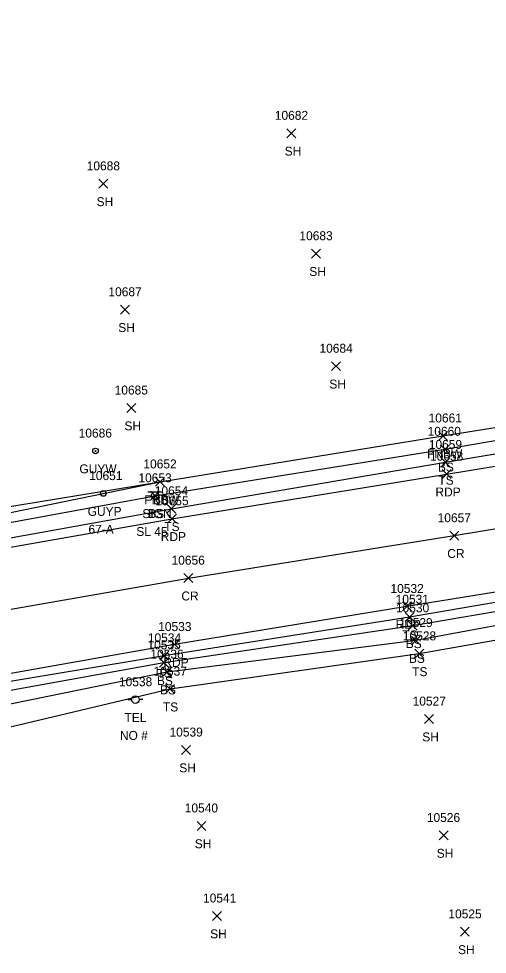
# Model space of a CAD drawing. Extents: x 1475671 to 1477951, y 592661 to 593821.
# Drawn here: x 1475962.2 to 1476066.9, y 592891.1 to 593100.2 of the extents above; entities that cross this region are included whole.
import ezdxf

# ---------------------------------------------------------------- set-up
doc = ezdxf.new("R2010")
doc.units = 0
for name, color, linetype in [('L_A', 7, 'Continuous'), ('L_I', 7, 'Continuous'), ('L_TIC', 7, 'Continuous'), ('LELB', 7, 'Continuous'), ('LFNC', 7, 'Continuous'), ('P_A', 7, 'Continuous'), ('P_I', 7, 'Continuous'), ('P_TIC', 7, 'Continuous'), ('PET', 7, 'Continuous'), ('PRC', 7, 'Continuous'), ('S_A', 7, 'Continuous'), ('S_C', 7, 'Continuous'), ('S_I', 7, 'Continuous'), ('SSGN', 7, 'Continuous'), ('U_A', 7, 'Continuous'), ('U_C', 7, 'Continuous'), ('U_I', 7, 'Continuous'), ('UP', 7, 'Continuous'), ('UPGW', 7, 'Continuous')]:
    doc.layers.add(name, color=color, linetype=linetype)

msp = doc.modelspace()

# ---------------------------------------------------------------- linework, layer by layer
at = {"layer": 'L_TIC'}
for points in [[(1476022.14, 593073.57), (1476024.14, 593075.57)], [(1476024.14, 593073.57), (1476022.14, 593075.57)], [(1475980.1, 593062.28), (1475982.1, 593064.28)], [(1475982.1, 593062.28), (1475980.1, 593064.28)], [(1476027.65, 593046.67), (1476029.65, 593048.67)], [(1476029.65, 593046.67), (1476027.65, 593048.67)], [(1475984.95, 593034.15), (1475986.95, 593036.15)], [(1475986.95, 593034.15), (1475984.95, 593036.15)], [(1476032.12, 593021.52), (1476034.12, 593023.52)], [(1476034.12, 593021.52), (1476032.12, 593023.52)], [(1475986.34, 593012.18), (1475988.34, 593014.18)], [(1475988.34, 593012.18), (1475986.34, 593014.18)], [(1476055.99, 593005.94), (1476057.99, 593007.94)], [(1476057.99, 593005.94), (1476055.99, 593007.94)], [(1476056.44, 593002.96), (1476058.44, 593004.96)], [(1476058.44, 593002.96), (1476056.44, 593004.96)], [(1476056.58, 593000.03), (1476058.58, 593002.03)], [(1476058.58, 593000.03), (1476056.58, 593002.03)], [(1475992.78, 592995.67), (1475994.78, 592997.67)], [(1475994.78, 592995.67), (1475992.78, 592997.67)], [(1475992.78, 592995.67), (1475994.78, 592997.67)], [(1475994.78, 592995.67), (1475992.78, 592997.67)], [(1475991.67, 592992.57), (1475993.67, 592994.57)], [(1475993.67, 592992.57), (1475991.67, 592994.57)], [(1475995.32, 592989.67), (1475997.32, 592991.67)], [(1475997.32, 592989.67), (1475995.32, 592991.67)], [(1476048.54, 592965.45), (1476050.54, 592967.45)], [(1476050.54, 592965.45), (1476048.54, 592967.45)], [(1476049.25, 592963.51), (1476051.25, 592965.51)], [(1476051.25, 592963.51), (1476049.25, 592965.51)], [(1476049.95, 592960.21), (1476051.95, 592962.21)], [(1476051.95, 592960.21), (1476049.95, 592962.21)], [(1476050.72, 592957.25), (1476052.72, 592959.25)], [(1476052.72, 592957.25), (1476050.72, 592959.25)], [(1475993.64, 592955.24), (1475995.64, 592957.24)], [(1475995.64, 592955.24), (1475993.64, 592957.24)], [(1475993.72, 592956.82), (1475995.72, 592958.82)], [(1475995.72, 592956.82), (1475993.72, 592958.82)], [(1475994.34, 592953.17), (1475996.34, 592955.17)], [(1475996.34, 592953.17), (1475994.34, 592955.17)], [(1475995.01, 592949.36), (1475997.01, 592951.36)], [(1475997.01, 592949.36), (1475995.01, 592951.36)], [(1476052.9, 592942.67), (1476054.9, 592944.67)], [(1476054.9, 592942.67), (1476052.9, 592944.67)], [(1475998.58, 592935.75), (1476000.58, 592937.75)], [(1476000.58, 592935.75), (1475998.58, 592937.75)], [(1476002.05, 592918.79), (1476004.05, 592920.79)], [(1476004.05, 592918.79), (1476002.05, 592920.79)], [(1476056.14, 592916.66), (1476058.14, 592918.66)], [(1476058.14, 592916.66), (1476056.14, 592918.66)], [(1476005.5, 592898.66), (1476007.5, 592900.66)], [(1476007.5, 592898.66), (1476005.5, 592900.66)], [(1476060.9, 592895.12), (1476062.9, 592897.12)], [(1476062.9, 592895.12), (1476060.9, 592897.12)]]:
    msp.add_lwpolyline(points, dxfattribs=at)
at = {"layer": 'LELB'}
for points in [[(1475681.97, 592926.29), (1475693.99, 592930.92), (1475717.71, 592935.95), (1475764.49, 592948.74), (1475792.84, 592955.38), (1475826.76, 592965.2), (1475839.14, 592967.57), (1475847.44, 592968.45), (1475896, 592975.83), (1475948.75, 592985.5), (1475992.67, 592993.57), (1476057.44, 593003.96), (1476113.1, 593013.57), (1476163.64, 593021.28), (1476215.98, 593029.82), (1476272.69, 593037.85), (1476322.72, 593046.24), (1476372.45, 593058.02), (1476374.59, 593060.62), (1476398.56, 593065.83), (1476415.47, 593071.31), (1476457.34, 593084.84)], [(1475681.68, 592929.89), (1475693.99, 592930.92), (1475717.95, 592934.41), (1475766.45, 592946.03), (1475793.6, 592952.64), (1475827.75, 592961.96), (1475839.66, 592963.32), (1475897.61, 592972.89), (1475949.51, 592982.21), (1475996.32, 592990.67), (1476057.58, 593001.03), (1476113.5, 593010.46), (1476164.33, 593018.66), (1476216.45, 593027.16), (1476273.17, 593035.57), (1476322.97, 593043.9), (1476372.64, 593054.79), (1476374.63, 593058.12)], [(1476521.14, 593041.18), (1476464.22, 593030.64), (1476420.77, 593020.64), (1476368.55, 593014.29), (1476359.82, 593012.38), (1476319.88, 593006.6), (1476267.05, 592998.99), (1476216.33, 592991.85), (1476164.01, 592984.31), (1476119.67, 592976.43), (1476101.12, 592973.12), (1476050.25, 592964.51), (1475994.64, 592956.24), (1475948.73, 592947.98), (1475899.49, 592939.5), (1475855.9, 592931.1), (1475802.57, 592920.15), (1475791.75, 592916.74), (1475792.51, 592914.78)], [(1476534.65, 593028.56), (1476525.69, 593019.5), (1476511.54, 593017.85), (1476467.31, 593015.01), (1476422.73, 593008.46), (1476366.85, 593001.28), (1476356.63, 592997.77), (1476347.04, 593000.45), (1476320.8, 592997.35), (1476267.98, 592990.13), (1476216.9, 592984.46), (1476165.76, 592976.73), (1476117.9, 592968.73), (1476100.74, 592966.91), (1476051.72, 592958.25), (1475996.01, 592950.36), (1475948.39, 592939), (1475900.82, 592931.75), (1475857.92, 592923.91), (1475803.59, 592912.34), (1475790.59, 592904.71)], [(1476511.04, 593028.14), (1476465.56, 593023.07), (1476421.22, 593014.7), (1476366.44, 593009.67), (1476355.54, 593008.55), (1476320.37, 593003.18), (1476267.54, 592995.9), (1476216.93, 592987.92), (1476164.84, 592980.53), (1476118, 592971.7), (1476100.88, 592970.48), (1476050.95, 592961.21), (1475995.34, 592954.17), (1475949.24, 592944.73), (1475901.01, 592937.79), (1475856.17, 592929.37), (1475802.39, 592917.73), (1475792.51, 592914.78)], [(1475847.44, 592968.45), (1475847.47, 592971.97), (1475895.33, 592978.11), (1475948.32, 592987.38), (1475993.78, 592996.67)], [(1476119.67, 592976.43), (1476100.91, 592975.21), (1476049.54, 592966.45), (1475994.72, 592957.82), (1475948.15, 592950.07), (1475899.13, 592941.1), (1475855.65, 592932.47), (1475802.49, 592921.46), (1475788.48, 592918.16)]]:
    msp.add_lwpolyline(points, dxfattribs=at)
at = {"layer": 'LFNC'}
msp.add_lwpolyline([(1475680.63, 592937.28), (1475715.61, 592943.34), (1475763.84, 592955.14), (1475791.92, 592961.08), (1475824.89, 592967.76), (1475839.13, 592970.46), (1475847.47, 592971.97), (1475895.02, 592980.45), (1475948.31, 592989.25), (1475993.78, 592996.67), (1476056.99, 593006.94), (1476113.81, 593016.03), (1476164.23, 593025.08), (1476215.07, 593032.59), (1476272.43, 593042.08), (1476322.23, 593049.67), (1476368.09, 593057.49), (1476372.45, 593058.02), (1476374.63, 593058.12), (1476399.83, 593064.01), (1476415.89, 593069.22), (1476458.99, 593083.01), (1476499.73, 593099.84)], dxfattribs=at)
at = {"layer": 'P_TIC'}
for points in [[(1476056.84, 592997.4), (1476058.84, 592999.4)], [(1476058.84, 592997.4), (1476056.84, 592999.4)], [(1475995.45, 592987.43), (1475997.45, 592989.43)], [(1475997.45, 592987.43), (1475995.45, 592989.43)], [(1476058.54, 592983.65), (1476060.54, 592985.65)], [(1476060.54, 592983.65), (1476058.54, 592985.65)], [(1475999.12, 592974.16), (1476001.12, 592976.16)], [(1476001.12, 592974.16), (1475999.12, 592976.16)], [(1476047.95, 592967.83), (1476049.95, 592969.83)], [(1476049.95, 592967.83), (1476047.95, 592969.83)], [(1475996.04, 592959.32), (1475998.04, 592961.32)], [(1475998.04, 592959.32), (1475996.04, 592961.32)]]:
    msp.add_lwpolyline(points, dxfattribs=at)
at = {"layer": 'PET'}
for points in [[(1475682.06, 592924.71), (1475717.58, 592931.68), (1475766.32, 592943.31), (1475794.98, 592949.79), (1475825.77, 592956.33), (1475844.1, 592960.26), (1475899.54, 592970.95), (1475949.72, 592980.21), (1475996.45, 592988.43), (1476057.84, 592998.4), (1476110.05, 593006.96), (1476164.18, 593015.73), (1476216.75, 593023.76), (1476273.83, 593032.32), (1476323.32, 593041.42), (1476373.65, 593052.29), (1476409.24, 593061.35), (1476416.16, 593063.9), (1476459.25, 593078.48), (1476508.39, 593100.17)], [(1476521.33, 593044.37), (1476462.5, 593038.2), (1476408.69, 593032.05), (1476367.34, 593022.2), (1476318.64, 593012.07), (1476266.69, 593003.36), (1476216.58, 592995.35), (1476163.86, 592987.33), (1476119.65, 592980.05), (1476101.05, 592977.22), (1476048.95, 592968.83), (1475997.04, 592960.32), (1475947.8, 592951.63), (1475898.72, 592942.8), (1475855.26, 592933.74), (1475801.94, 592923.33), (1475788.88, 592919.68), (1475771.17, 592916.5), (1475722.69, 592905.51), (1475685.82, 592897.63)]]:
    msp.add_lwpolyline(points, dxfattribs=at)
at = {"layer": 'PRC'}
msp.add_lwpolyline([(1475683.62, 592911.01), (1475719.65, 592918.7), (1475759.33, 592927.39), (1475790.86, 592934.39), (1475834.03, 592943.87), (1475901.67, 592957.18), (1475953.57, 592967.02), (1476000.12, 592975.16), (1476059.54, 592984.65), (1476113.3, 592993.58), (1476166.39, 593001.74), (1476218.93, 593009.6), (1476277, 593018.86), (1476325.59, 593027.6), (1476377.06, 593038.84), (1476415.44, 593049.14), (1476421.8, 593050.95), (1476461.98, 593064.62), (1476520.7, 593090.52)], dxfattribs=at)
at = {"layer": 'SSGN'}
for p, q in [((1475991.04, 592994.42), (1475994.38, 592994.42)), ((1475992.69, 592993.59), (1475992.69, 592993.59))]:
    msp.add_line(p, q, dxfattribs=at)
msp.add_circle((1475992.69, 592993.59), 0.833, dxfattribs=at)
at = {"layer": 'UP'}
for p, q in [((1475986.61, 592948), (1475987.44, 592948)), ((1475988.27, 592948), (1475988.27, 592948)), ((1475989.94, 592948), (1475989.11, 592948)), ((1475989.11, 592948), (1475989.11, 592948)), ((1475989.94, 592948), (1475989.94, 592948))]:
    msp.add_line(p, q, dxfattribs=at)
msp.add_circle((1475988.27, 592948), 0.833, dxfattribs=at)
at = {"layer": 'UPGW'}
for centre, radius in [((1475979.36, 593003.57), 0.625), ((1475979.36, 593003.57), 0.0833), ((1475981.09, 592994.06), 0.625), ((1475981.09, 592994.06), 0.0833)]:
    msp.add_circle(centre, radius, dxfattribs=at)

# ---------------------------------------------------------------- texts
at = {"layer": 'L_A'}
for s, p in [('SH', (1476021.63, 593069.57)), ('SH', (1475979.59, 593058.28)), ('SH', (1476027.14, 593042.67)), ('SH', (1475984.44, 593030.15)), ('SH', (1476031.61, 593017.52)), ('SH', (1475985.83, 593008.18)), ('FNBW', (1476053.47, 593001.94)), ('BS', (1476055.88, 592998.96)), ('TS', (1476055.99, 592996.03)), ('FNBW', (1475990.25, 592991.67)), ('BS', (1475992.22, 592991.67)), ('BS', (1475991.11, 592988.57)), ('TS', (1475994.72, 592985.67)), ('TS', (1476047.95, 592961.45)), ('BS', (1476048.69, 592959.51)), ('BS', (1476049.39, 592956.21)), ('TS', (1476050.13, 592953.25)), ('TS', (1475993.13, 592952.82)), ('BS', (1475993.08, 592951.24)), ('BS', (1475993.78, 592949.17)), ('TS', (1475994.42, 592945.36)), ('SH', (1476052.39, 592938.67)), ('SH', (1475998.07, 592931.75)), ('SH', (1476001.54, 592914.79)), ('SH', (1476055.62, 592912.66)), ('SH', (1476004.98, 592894.66)), ('SH', (1476060.39, 592891.12))]:
    msp.add_text(s, height=2, dxfattribs=at).set_placement(p)
at = {"layer": 'L_I'}
for s, p in [('10682', (1476019.43, 593077.57)), ('10688', (1475977.39, 593066.28)), ('10683', (1476024.93, 593050.67)), ('10687', (1475982.24, 593038.15)), ('10684', (1476029.41, 593025.52)), ('10685', (1475983.63, 593016.18)), ('10661', (1476053.8, 593009.94)), ('10660', (1476053.59, 593006.96)), ('10659', (1476053.85, 593004.03)), ('10652', (1475990.06, 592999.67)), ('10652', (1475990.06, 592999.67)), ('10653', (1475988.95, 592996.57)), ('10654', (1475992.6, 592993.67)), ('10531', (1476046.44, 592969.45)), ('10530', (1476046.5, 592967.51)), ('10529', (1476047.28, 592964.21)), ('10534', (1475991.05, 592960.82)), ('10528', (1476048.05, 592961.25)), ('10535', (1475990.97, 592959.24)), ('10536', (1475991.62, 592957.17)), ('10537', (1475992.34, 592953.36)), ('10527', (1476050.23, 592946.67)), ('10539', (1475995.9, 592939.75)), ('10540', (1475999.3, 592922.79)), ('10526', (1476053.41, 592920.66)), ('10541', (1476003.39, 592902.66)), ('10525', (1476058.23, 592899.12))]:
    msp.add_text(s, height=2, dxfattribs=at).set_placement(p)
at = {"layer": 'P_A'}
for s, p in [('RDP', (1476055.33, 592993.4)), ('RDP', (1475993.94, 592983.43)), ('CR', (1476057.97, 592979.65)), ('CR', (1475998.55, 592970.16)), ('RDP', (1476046.44, 592963.83)), ('RDP', (1475994.53, 592955.32))]:
    msp.add_text(s, height=2, dxfattribs=at).set_placement(p)
at = {"layer": 'P_I'}
for s, p in [('10658', (1476054.12, 593001.4)), ('10655', (1475992.73, 592991.43)), ('10657', (1476055.82, 592987.65)), ('10656', (1475996.35, 592978.16)), ('10532', (1476045.28, 592971.83)), ('10533', (1475993.37, 592963.32))]:
    msp.add_text(s, height=2, dxfattribs=at).set_placement(p)
at = {"layer": 'S_A'}
msp.add_text('SIGN', height=2, dxfattribs=at).set_placement((1475989.83, 592988.57))
at = {"layer": 'S_C'}
msp.add_text('SL 45', height=2, dxfattribs=at).set_placement((1475988.47, 592984.57))
at = {"layer": 'S_I'}
msp.add_text('10653', height=2, dxfattribs=at).set_placement((1475988.95, 592996.57))
at = {"layer": 'U_A'}
for s, p in [('GUYW', (1475975.76, 592998.57)), ('GUYP', (1475977.6, 592989.06)), ('TEL', (1475985.83, 592943))]:
    msp.add_text(s, height=2, dxfattribs=at).set_placement(p)
at = {"layer": 'U_C'}
for s, p in [('67-A', (1475977.78, 592985.06)), ('NO #', (1475984.81, 592939))]:
    msp.add_text(s, height=2, dxfattribs=at).set_placement(p)
at = {"layer": 'U_I'}
for s, p in [('10686', (1475975.59, 593006.57)), ('10651', (1475977.94, 592997.06)), ('10538', (1475984.6, 592951))]:
    msp.add_text(s, height=2, dxfattribs=at).set_placement(p)

doc.saveas('drawing.dxf')
